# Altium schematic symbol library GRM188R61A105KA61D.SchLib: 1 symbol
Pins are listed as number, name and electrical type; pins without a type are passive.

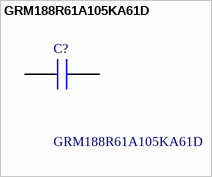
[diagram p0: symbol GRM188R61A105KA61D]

## GRM188R61A105KA61D
designator C?
Ceramic  SMT capacitor 1uF 10Vdc Murata 0603 GRM 1uF Ceramic Multilayer Capacitor, 10 V dc, +85C, X5R Dielectric, +/-10%; Manufacturer_Name: Murata Electronics; Geometry.Height: 0.9mm
footprint CAPC1608X90N
pins: 1, 2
